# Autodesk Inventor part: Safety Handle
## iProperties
Shininess: 77.0
Length Units: 11269
Angle Units: 11279
Time Units: 11290
Mass Units: 11283
Length Display Precision: 3
Angle Display Precision: 2
Created: 2002-02
Part Number: Safety Handle
Document SubType Name: Modeling
Designer: ***
Density: 0.0
Volumn: 0.0
Area: 0.0
PropertySet Name: Model Information
Control State: 0
Master: False
Checked Out: False
Author: ***
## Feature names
1. Revolution1
2. Revolution2
